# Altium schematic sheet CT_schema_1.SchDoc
size 504 x 258 mm
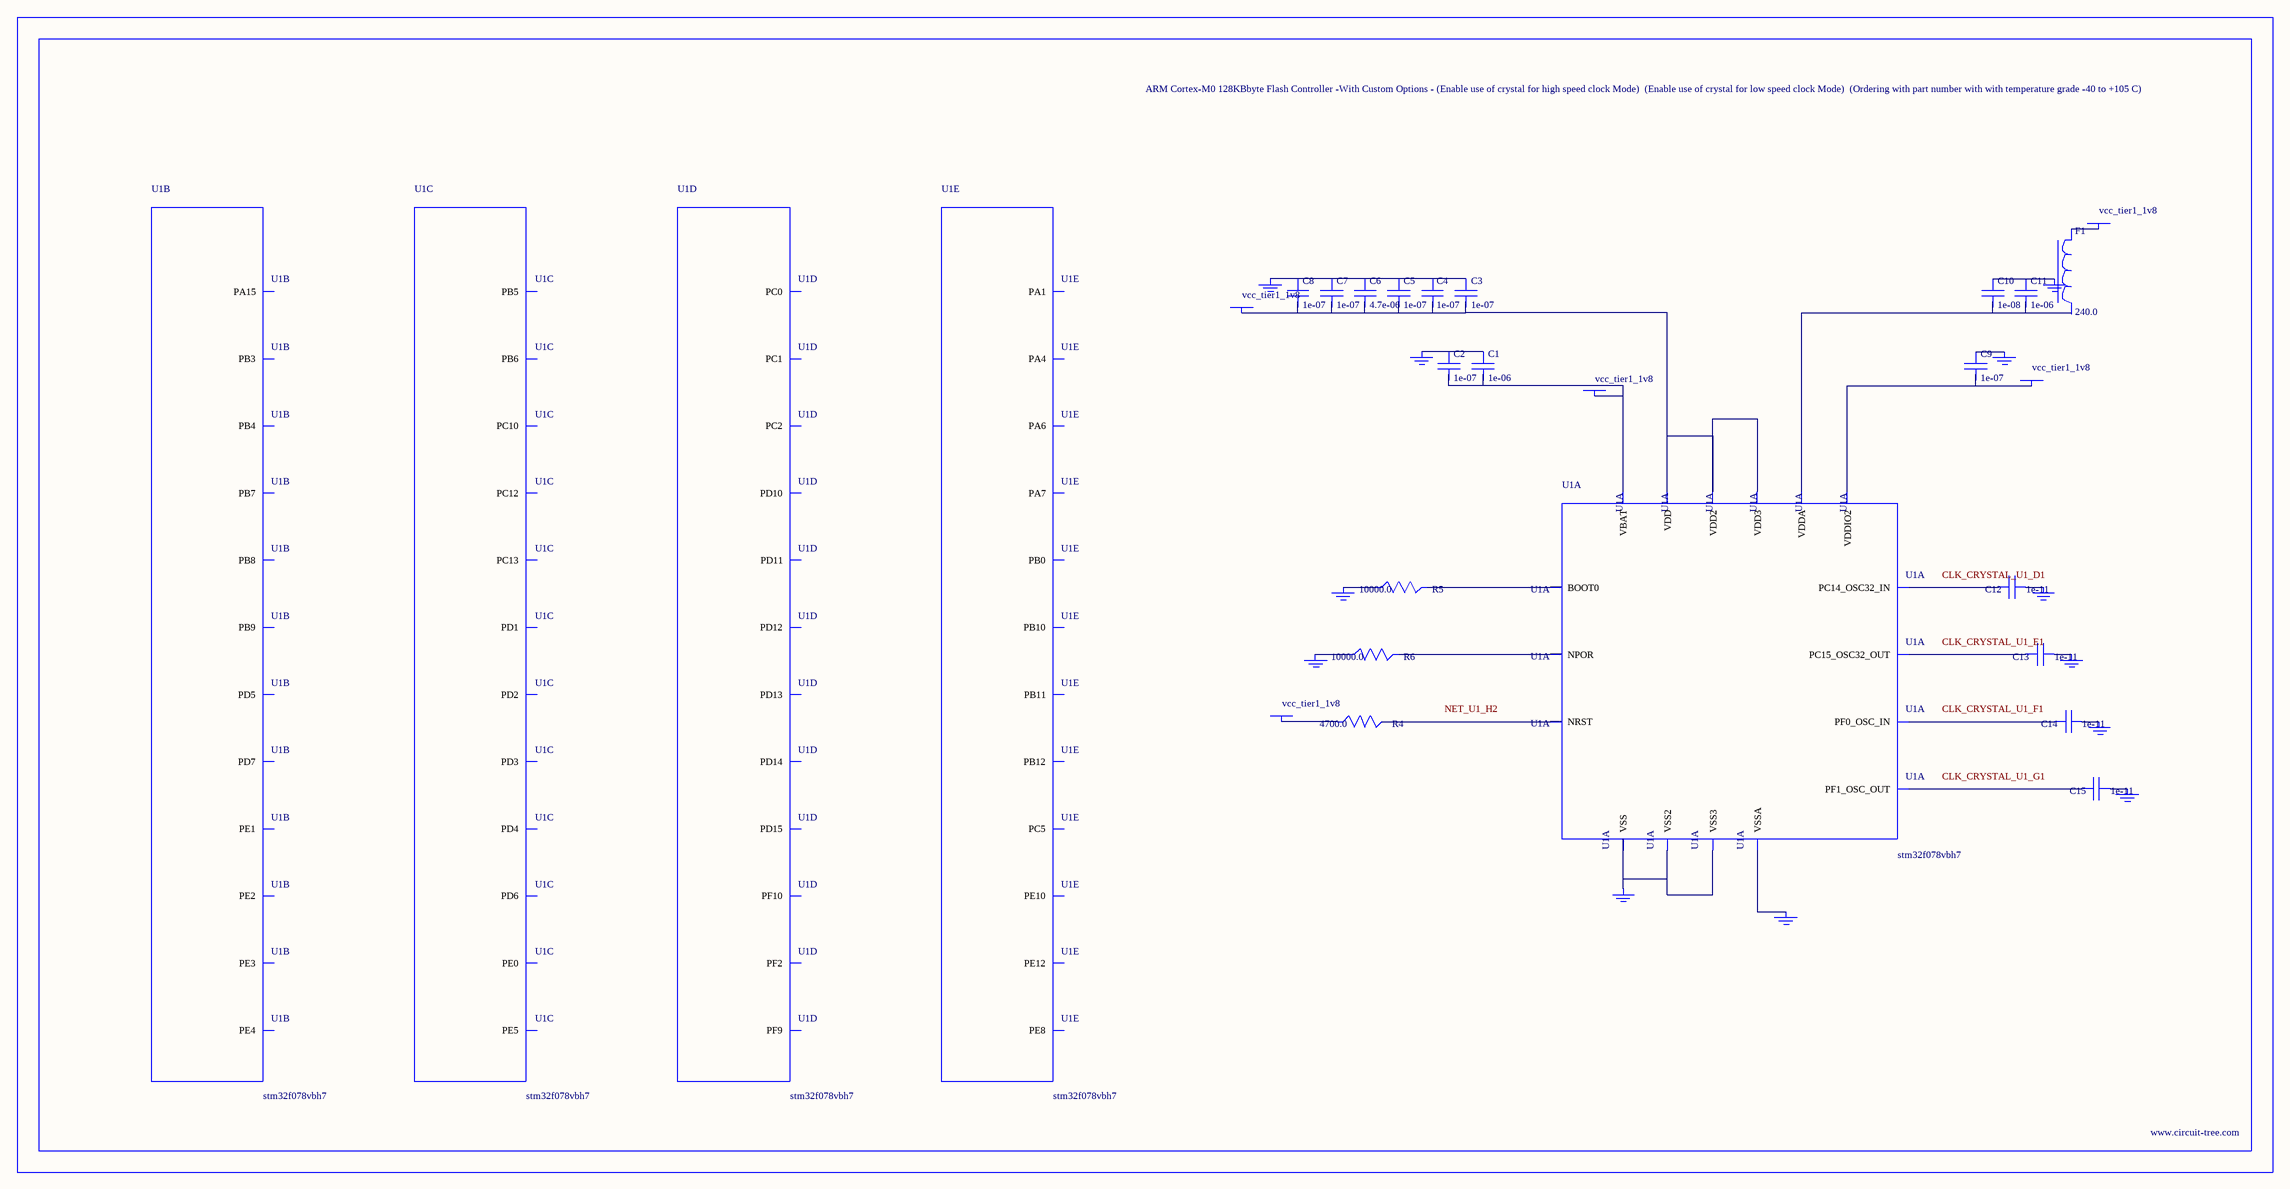
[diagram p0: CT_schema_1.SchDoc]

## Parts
BORDER0  (no value)
C1  1e-06  [C0603]
C2  1e-07  [C0603]
C3  1e-07  [C0603]
C4  1e-07  [C0603]
C5  1e-07  [C0603]
C6  4.7e-06  [C0603]
C7  1e-07  [C0603]
C8  1e-07  [C0603]
C9  1e-07  [C0603]
C10  1e-08  [C0603]
C11  1e-06  [C0603]
C12  1e-11  [C0402]
C13  1e-11  [C0402]
C14  1e-11  [C0402]
C15  1e-11  [C0402]
F1  240.0  [L0603]
GND_INSTANCE_0_0  (no value)
GND_INSTANCE_0_1  (no value)
GND_INSTANCE_0_2  (no value)
GND_INSTANCE_0_3  (no value)
GND_INSTANCE_0_4  (no value)
GND_INSTANCE_0_5  (no value)
GND_INSTANCE_0_6  (no value)
GND_INSTANCE_0_7  (no value)
GND_INSTANCE_0_8  (no value)
GND_INSTANCE_0_9  (no value)
GND_INSTANCE_0_10  (no value)
GND_INSTANCE_0_11  (no value)
POWER_INSTANCE_0_0  vcc_tier1_1v8
POWER_INSTANCE_0_1  vcc_tier1_1v8
POWER_INSTANCE_0_2  vcc_tier1_1v8
POWER_INSTANCE_0_3  vcc_tier1_1v8
POWER_INSTANCE_0_4  vcc_tier1_1v8
R4  4700.0  [R0603]
R5  10000.0  [R0603]
R6  10000.0  [R0603]
U1  stm32f078vbh7  [UFBGA100]  (parts A,B,C,D,E of 9)

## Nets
NetC1_1: C1.1 C2.1 GND_INSTANCE_0_0.0(GND)
NetC1_2: C1.2 C2.2 POWER_INSTANCE_0_0.0(PWR) U1.E2(VBAT)
NetC3_1: C3.1 C4.1 C5.1 C6.1 C7.1 C8.1 GND_INSTANCE_0_2.0(GND)
NetC3_2: C3.2 C4.2 C5.2 C6.2 C7.2 C8.2 POWER_INSTANCE_0_2.0(PWR) U1.C4(VDD) U1.G12(VDD2) U1.H3(VDD3)
NetC9_1: C9.1 GND_INSTANCE_0_3.0(GND)
NetC9_2: C9.2 POWER_INSTANCE_0_3.0(PWR) U1.G11(VDDIO2)
NetC10_1: C10.1 C11.1 GND_INSTANCE_0_1.0(GND)
NetC10_2: C10.2 C11.2 U1.M1(VDDA)
NetC12_1: C12.1 GND_INSTANCE_0_6.0(GND)
NetC12_2: C12.2 U1.D1(PC14_OSC32_IN)
NetC13_1: C13.1 GND_INSTANCE_0_7.0(GND)
NetC13_2: C13.2 U1.E1(PC15_OSC32_OUT)
NetC14_1: C14.1 GND_INSTANCE_0_8.0(GND)
NetC14_2: C14.2 U1.F1(PF0_OSC_IN)
NetC15_1: C15.1 GND_INSTANCE_0_9.0(GND)
NetC15_2: C15.2 U1.G1(PF1_OSC_OUT)
NetF1_1: F1.1 POWER_INSTANCE_0_1.0(PWR)
NetGND_INSTANCE_0_4_0: GND_INSTANCE_0_4.0(GND) R5.1
NetGND_INSTANCE_0_5_0: GND_INSTANCE_0_5.0(GND) R6.1
NetGND_INSTANCE_0_10_0: GND_INSTANCE_0_10.0(GND) U1.K1(VSSA)
NetGND_INSTANCE_0_11_0: GND_INSTANCE_0_11.0(GND) U1.D3(VSS) U1.F11(VSS2) U1.F12(VSS3)
NetPOWER_INSTANCE_0_4_0: POWER_INSTANCE_0_4.0(PWR) R4.1
NetR4_2: R4.2 U1.H2(NRST)
NetR5_2: R5.2 U1.A4(BOOT0)
NetR6_2: R6.2 U1.L6(NPOR)

Not connected (* = marked no-connect by the designer): F1 2; U1 A1(PE3) A2(PE1) A3(PB8) A5(PD7) A6(PD5) A7(PB4) A8(PB3) A9(PA15) B1(PE4) B2(PE2) B3(PB9) B4(PB7) B5(PB6) B6(PD6) B7(PD4) B8(PD3) B9(PD1) B10(PC12) B11(PC10) C1(PC13) C2(PE5) C3(PE0) C5(PB5) C8(PD2) F2(PF9) G2(PF10) H1(PC0) H10(PD15) H11(PD14) H12(PD13) J1(PF2) J2(PC1) J3(PC2) J10(PD12) J11(PD11) J12(PD10) L4(PA6) L5(PC5) L7(PE8) L8(PE10) L9(PE12) L10(PB10) L11(PB11) L12(PB12) M2(PA1) M3(PA4) M4(PA7) M5(PB0)

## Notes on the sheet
- Labels drawn without touching a wire or pin: CLK_CRYSTAL_U1_D1, CLK_CRYSTAL_U1_E1, CLK_CRYSTAL_U1_F1, CLK_CRYSTAL_U1_G1, NET_U1_H2

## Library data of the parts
BORDER0 = BORDER_PAGE0
C1 C11 = C0603C105K3RACTU
C2-C5 C7-C9 = 06035C104K4Z2A
C6 = GRM188R6YA475KE15D
C10 = 06035C103K4Z2A
C12-C15 = C0402C100K3GACTU
F1 = Z0603C241ASMST
GND_INSTANCE_0_0-GND_INSTANCE_0_11 = GND
POWER_INSTANCE_0_0-POWER_INSTANCE_0_4 = PWR
R4 = RC0603JR-074K7L
R5 R6 = RC0603JR-0710KL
